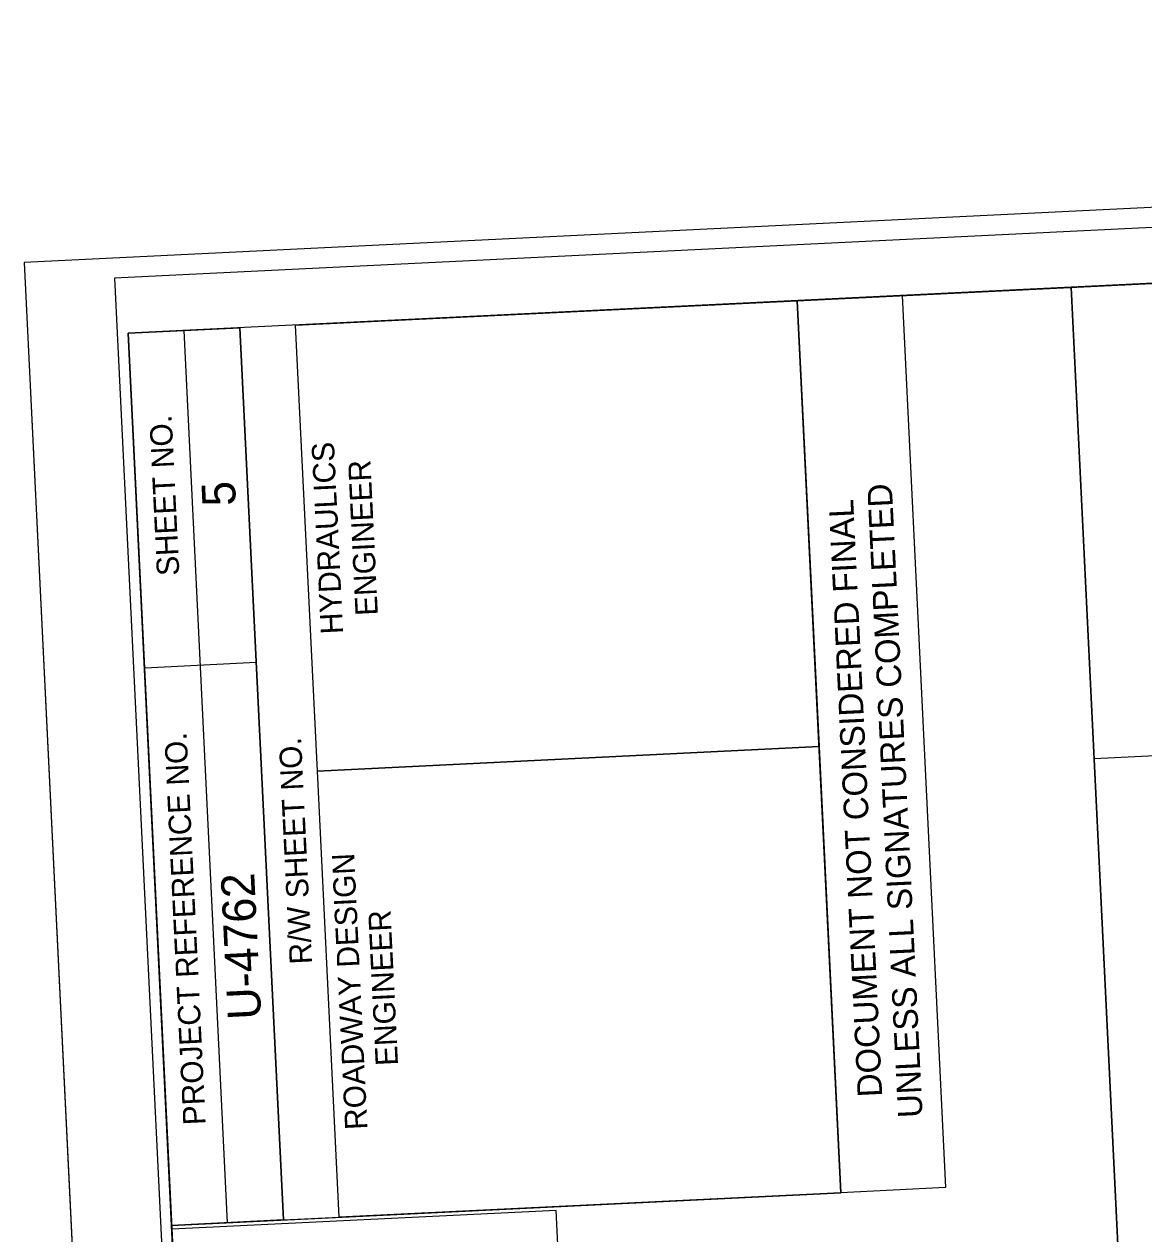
# Model space of a CAD drawing. Extents: x 2368277 to 2369452, y 801942 to 803676.
# Drawn here: x 2368276.7 to 2368527.5, y 803405.5 to 803676.4 of the extents above; entities that cross this region are included whole.
import ezdxf

# ---------------------------------------------------------------- set-up
doc = ezdxf.new("R2010")
doc.units = 0
for name, color, linetype in [('Old_Level_10', 7, 'Continuous'), ('Old_Level_15', 7, 'Continuous'), ('Old_Level_2', 7, 'Continuous'), ('Old_Level_4', 7, 'Continuous'), ('Old_Level_6', 7, 'Continuous'), ('Old_Level_7', 7, 'Continuous'), ('Plan Sheet CELL', 7, 'Continuous'), ('Plot Label CELL', 7, 'Continuous'), ('Plot Shape CELL', 7, 'Continuous')]:
    doc.layers.add(name, color=color, linetype=linetype)

msp = doc.modelspace()

# ---------------------------------------------------------------- linework, layer by layer
at = {"layer": 'Old_Level_10'}
for points in [[(2368373.13, 802108.95), (2369421.86, 802160.14), (2369348.77, 803658.36), (2368511.25, 803617.5), (2368522.91, 803378.54), (2368311.67, 803368.23)], [(2368522.91, 803378.54), (2368511.25, 803617.53), (2368300.01, 803607.25), (2368311.67, 803368.23)]]:
    msp.add_lwpolyline(points, close=True, dxfattribs=at)
at = {"layer": 'Old_Level_15'}
msp.add_line((2368276.72, 803623.09), (2368358.75, 801941.59), dxfattribs=at)
at = {"layer": 'Old_Level_2'}
msp.add_lwpolyline([(2369296.9, 802302.46), (2369299.46, 802249.75), (2368368.59, 802201.94), (2368311.67, 803368.23), (2368522.91, 803378.54), (2368516.4, 803511.97), (2369216.72, 803546.4), (2369252.92, 803653.7), (2369348.77, 803658.37), (2369414.6, 802308.91)], close=True, dxfattribs=at)
msp.add_lwpolyline([(2369296.9, 802302.46), (2369299.46, 802249.75), (2368368.59, 802201.94), (2368311.67, 803368.23), (2368522.91, 803378.54), (2368516.4, 803511.97), (2369216.72, 803546.4), (2369252.92, 803653.7), (2369348.77, 803658.37), (2369414.6, 802308.91)], close=True, dxfattribs=at)
at = {"layer": 'Old_Level_4'}
msp.add_lwpolyline([(2369431.84, 802006.96), (2369350.65, 803670.97), (2368296.92, 803619.57), (2368378.1, 801955.55)], close=True, dxfattribs=at)
at = {"layer": 'Old_Level_6'}
msp.add_lwpolyline([(2369452.45, 801994.95), (2369370.42, 803676.45), (2368276.72, 803623.09), (2368358.75, 801941.59)], close=True, dxfattribs=at)
at = {"layer": 'Old_Level_7'}
msp.add_lwpolyline([(2368309.8, 803406.54), (2368314.67, 803306.78), (2368400.72, 803310.97), (2368395.85, 803410.73)], close=True, dxfattribs=at)
at = {"layer": 'Plan Sheet CELL'}
for p, q in [((2368449.9, 803614.52), (2368473.37, 803615.67)), ((2368449.9, 803614.52), (2368473.37, 803615.67)), ((2368473.36, 803615.67), (2368483.1, 803415.87)), ((2368473.36, 803615.67), (2368483.1, 803415.87)), ((2368459.63, 803414.72), (2368449.88, 803614.52)), ((2368459.63, 803414.72), (2368449.88, 803614.52)), ((2368483.1, 803415.87), (2368459.63, 803414.72)), ((2368483.1, 803415.87), (2368459.63, 803414.72))]:
    msp.add_line(p, q, dxfattribs=at)
at = {"layer": 'Plot Shape CELL'}
for p, q in [((2368322.28, 803407.99), (2368312.55, 803607.81)), ((2368334.81, 803408.62), (2368325.03, 803608.42)), ((2368334.81, 803408.62), (2368325.03, 803608.42)), ((2368303.73, 803532.26), (2368328.7, 803533.53)), ((2368342.4, 803509.16), (2368454.73, 803514.65)), ((2368334.81, 803408.62), (2368347.28, 803409.23))]:
    msp.add_line(p, q, dxfattribs=at)
for points in [[(2368300.01, 803607.23), (2368373.1, 802108.98), (2369421.86, 802160.14), (2369348.77, 803658.37)], [(2369421.86, 802160.14), (2368373.13, 802108.95), (2368309.75, 803407.4), (2368459.63, 803414.72), (2368449.9, 803614.52), (2369348.77, 803658.37)], [(2368342.4, 803509.16), (2368337.52, 803609.03), (2368449.9, 803614.52), (2368454.78, 803514.64)], [(2368309.75, 803407.4), (2368300.01, 803607.23), (2368325.03, 803608.42), (2368334.81, 803408.62)], [(2368347.28, 803409.23), (2368342.4, 803509.16), (2368454.78, 803514.64), (2368459.63, 803414.72)]]:
    msp.add_lwpolyline(points, close=True, dxfattribs=at)

# ---------------------------------------------------------------- texts
at = {"layer": 'Plan Sheet CELL'}
for s, p in [('UNLESS ALL SIGNATURES COMPLETED', (2368477.98, 803431.63)), ('UNLESS ALL SIGNATURES COMPLETED', (2368477.98, 803431.63)), ('DOCUMENT NOT CONSIDERED FINAL', (2368468.94, 803436.27)), ('DOCUMENT NOT CONSIDERED FINAL', (2368468.94, 803436.27))]:
    msp.add_text(s, height=5.5, rotation=92.7929, dxfattribs=at).set_placement(p)
at = {"layer": 'Plot Label CELL'}
for s, p in [('5', (2368324.17, 803568.68)), ('U-4762', (2368329.84, 803453.66))]:
    msp.add_text(s, height=7.5, rotation=92.7929, dxfattribs=at).set_placement(p)
at = {"layer": 'Plot Shape CELL'}
for s, height, p in [('SHEET NO.', 5, (2368311.49, 803553.02)), ('HYDRAULICS', 5, (2368348.19, 803539.94)), ('ENGINEER', 5, (2368355.96, 803544.08)), ('PROJECT REFERENCE NO.', 5.0001, (2368317.38, 803429.99)), ('R/W SHEET NO.', 5.0001, (2368341.21, 803466)), ('ROADWAY DESIGN', 5.0001, (2368353.63, 803428.93)), ('ENGINEER', 5, (2368360.47, 803443.27))]:
    msp.add_text(s, height=height, rotation=92.7929, dxfattribs=at).set_placement(p)

doc.saveas('drawing.dxf')
